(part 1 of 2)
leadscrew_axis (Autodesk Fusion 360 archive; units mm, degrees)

design "assy_leadscrew_axis" references "leadscrew_motor_mount", "HW_M5x30-FHCS", "HW_M5x40-FHCS", "HW_M3x16-SHCS", "HW_M3x8-SHCS", "HW_M5x10-FHCS", "HW_M3-Washer", "carriage_front_generic", "HW_M5 Nylock", "PP_TRNS_LeadNut-Block-8mm", "leadscrew_clip", "limit_mount", "lil_foot", "PP_ACTU_N17-Stepper-Leadscrew-300", "FRM-Extrusion-VSlot-2020-350", "circuit_mount_stepper_simple"
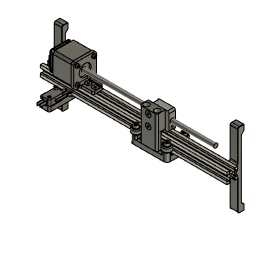
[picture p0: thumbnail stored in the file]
component_insert "Component Insert1"
joint "Assemble1" alignAngle -90 alignOffsetX 0 alignOffsetY 0 alignOffsetZ -6
component_insert "Component Insert2"
joint "Assemble2" alignAngle 0 alignOffsetX 0 alignOffsetY 80 alignOffsetZ 6
component_insert "Component Insert3"
joint "Assemble3" alignAngle -90 alignOffsetX 0 alignOffsetY 0 alignOffsetZ 0
component_insert "Component Insert4"
joint "Assemble4" alignAngle 180 alignOffsetX 0 alignOffsetY 0 alignOffsetZ 0
component_insert "Component Insert6"
joint "Assemble5" alignAngle 0 alignOffsetX 0 alignOffsetY 0 alignOffsetZ -10
component_insert "Component Insert7"
joint "Assemble6" alignAngle 270 alignOffsetX 0 alignOffsetY 53 alignOffsetZ 6
component_insert "Component Insert8"
joint "Assemble7" alignAngle 270 alignOffsetX 0 alignOffsetY 0 alignOffsetZ 0
joint "Assemble9" alignAngle 180 alignOffsetX 0 alignOffsetY 0 alignOffsetZ 0
component_insert "Component Insert9"
joint "Assemble10" alignAngle -90 alignOffsetX 0 alignOffsetY 0 alignOffsetZ 0
component_insert "Component Insert10"
component_insert "Component Insert11"
joint "Assemble11" alignAngle 0 alignOffsetX 0 alignOffsetY -10 alignOffsetZ 6
joint "Assemble12" alignAngle 0 alignOffsetX 0 alignOffsetY 10 alignOffsetZ 6
component_insert "Component Insert12"
joint "Assemble13" alignAngle 0 alignOffsetX 0 alignOffsetY 0 alignOffsetZ 0
component_insert "Component Insert13"
joint "Assemble14" alignAngle -90 alignOffsetX 0 alignOffsetY 0 alignOffsetZ 0
component_insert "Component Insert14"
component_insert "Component Insert15"
joint "Assemble15" alignAngle -90 alignOffsetX 0 alignOffsetY 0 alignOffsetZ 0
joint "Assemble16" alignAngle -90 alignOffsetX 0 alignOffsetY 0 alignOffsetZ 0
component_insert "Component Insert16"
component_insert "Component Insert17"
joint "Assemble17" alignAngle -90 alignOffsetX 0 alignOffsetY 0 alignOffsetZ 0
joint "Assemble18" alignAngle -90 alignOffsetX 0 alignOffsetY 0 alignOffsetZ 0
component_insert "Component Insert18"
component_insert "Component Insert19"
joint "Assemble19" alignAngle 90 alignOffsetX 0 alignOffsetY 0 alignOffsetZ 0
joint "Assemble20" alignAngle 90 alignOffsetX 0 alignOffsetY 0 alignOffsetZ 0
component_insert "Component Insert20"
component_insert "Component Insert21"
component_insert "Component Insert22"
joint "Assemble21" alignAngle 180 alignOffsetX 0 alignOffsetY 0 alignOffsetZ 0
joint "Assemble22" alignAngle -90 alignOffsetX 0 alignOffsetY 0 alignOffsetZ 0
joint "Assemble23" alignAngle -90 alignOffsetX 0 alignOffsetY 0 alignOffsetZ 0
component_insert "Component Insert23"
component_insert "Component Insert24"
joint "Assemble24" alignAngle 60 alignOffsetX 0 alignOffsetY 0 alignOffsetZ 0
joint "Assemble25" alignAngle 60 alignOffsetX 0 alignOffsetY 0 alignOffsetZ 0
component_insert "Component Insert25"
component_insert "Component Insert26"
component_insert "Component Insert27"
component_insert "Component Insert28"
joint "Assemble26" alignAngle 90 alignOffsetX 0 alignOffsetY 0 alignOffsetZ 0
joint "Assemble27" alignAngle -90 alignOffsetX 0 alignOffsetY 0 alignOffsetZ 0
joint "Assemble28" alignAngle -90 alignOffsetX 0 alignOffsetY 0 alignOffsetZ 0
joint "Assemble29" alignAngle -90 alignOffsetX 0 alignOffsetY 0 alignOffsetZ 0
component_insert "Component Insert29"
component_insert "Component Insert30"
component_insert "Component Insert31"
component_insert "Component Insert32"
joint "Assemble30" alignAngle 0 alignOffsetX 0 alignOffsetY 0 alignOffsetZ 0
joint "Assemble31" alignAngle 0 alignOffsetX 0 alignOffsetY 0 alignOffsetZ 0
joint "Assemble32" alignAngle 0 alignOffsetX 0 alignOffsetY 0 alignOffsetZ 0
joint "Assemble33" alignAngle 0 alignOffsetX 0 alignOffsetY 0 alignOffsetZ 0
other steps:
joint_origin "JointOrigin1"
joint_origin "JointOrigin2"

design "PP_TRNS_Mini-V-Wheel"
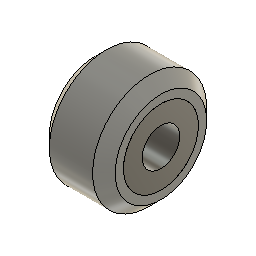
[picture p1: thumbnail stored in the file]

design "PP_TRNS_LeadNut-Block-8mm"
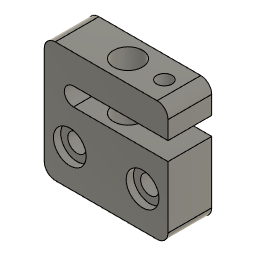
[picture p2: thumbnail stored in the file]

design "HW_M5x30-FHCS"
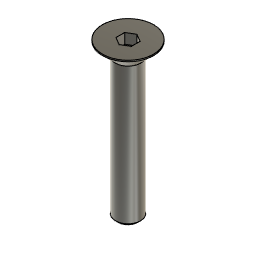
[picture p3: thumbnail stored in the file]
sketch "Sketch1" plane through (0, 0, 0) normal (0, 1, 0) x axis (1, 0, 0)
  line L1 (0, 30) -> (0, 0)
  line L2 (1.95, 30) -> (0, 30)
  line L3 (2.45, 29.5) -> (1.95, 30)
  line L4 (2.45, 2.8) -> (2.45, 29.5)
  line L5 (5, 0.25) -> (2.45, 2.8)
  line L6 (5, 0) -> (5, 0.25)
  line L7 (0, 0) -> (5, 0)
  point P1 (0, 0)
  point P2 (0, 0)
  point P9 (0, 0)
  point P3 (0, 30)
  point P4 (1.95, 30)
  point P8 (5, 0)
  point P7 (5, 0.25)
  coincident P1 P2
  vertical L1
  perpendicular L1 L2
  perpendicular L2 L4
  parallel L3 L5
  parallel L4 L6
  perpendicular L6 L7
  coincident P1 P9
  dimension "d1" distance P3 L4 = 2.45 (= "( 4.9 / 2 ) * 1 mm")
  dimension "d3" angle L2 L3 = 45
  dimension "d5" distance P4 L4 = 0.5
  dimension "d6" distance P2 P3 = 30
  dimension "d7" distance P8 P9 = 5 (= "( 10 / 2 ) * 1 mm")
  dimension "d9" distance P7 P8 = 0.25
revolve "Revolve1" sketch "Sketch1" AlongAngle 360
sketch "Sketch2" plane through (0, 0, 0) normal (0, 0, 1) x axis (-1, 0, 0)
  line L1 (0, -1.7321) -> (-1.5, -0.866)
  line L2 (1.5, -0.866) -> (0, -1.7321)
  line L3 (1.5, 0.866) -> (1.5, -0.866)
  line L4 (0, 1.7321) -> (1.5, 0.866)
  line L5 (-1.5, 0.866) -> (0, 1.7321)
  line L6 (-1.5, -0.866) -> (-1.5, 0.866)
  circle C1 centre (0, 0) radius 5
  point P1 (0, 0)
  point P9 (0, 0)
  coincident P1 P9
  vertical L6
  dimension "d12" distance L3 L6 = 3
extrude "Extrude1" cut sketch "Sketch2" profile of L1 L2 L3 L4 L5 L6 against normal blind 2

design "HW_M5x10-FHCS"
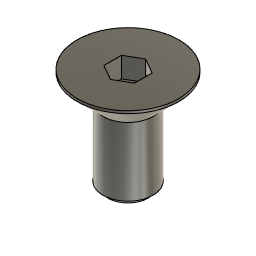
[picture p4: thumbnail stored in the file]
sketch "Sketch1" plane through (0, 0, 0) normal (0, 1, 0) x axis (1, 0, 0)
  line L1 (0, 10) -> (0, 0)
  line L2 (1.95, 10) -> (0, 10)
  line L3 (2.45, 9.5) -> (1.95, 10)
  line L4 (2.45, 2.8) -> (2.45, 9.5)
  line L5 (5, 0.25) -> (2.45, 2.8)
  line L6 (5, 0) -> (5, 0.25)
  line L7 (0, 0) -> (5, 0)
  point P1 (0, 0)
  point P2 (0, 0)
  point P9 (0, 0)
  point P3 (0, 10)
  point P4 (1.95, 10)
  point P8 (5, 0)
  point P7 (5, 0.25)
  coincident P1 P2
  vertical L1
  perpendicular L1 L2
  perpendicular L2 L4
  parallel L3 L5
  parallel L4 L6
  perpendicular L6 L7
  coincident P1 P9
  dimension "d1" distance P3 L4 = 2.45 (= "( 4.9 / 2 ) * 1 mm")
  dimension "d3" angle L2 L3 = 45
  dimension "d5" distance P4 L4 = 0.5
  dimension "d6" distance P2 P3 = 10
  dimension "d7" distance P8 P9 = 5 (= "( 10 / 2 ) * 1 mm")
  dimension "d9" distance P7 P8 = 0.25
revolve "Revolve1" sketch "Sketch1" AlongAngle 360
sketch "Sketch2" plane through (0, 0, 0) normal (0, 0, 1) x axis (-1, 0, 0)
  line L1 (0, -1.7321) -> (-1.5, -0.866)
  line L2 (1.5, -0.866) -> (0, -1.7321)
  line L3 (1.5, 0.866) -> (1.5, -0.866)
  line L4 (0, 1.7321) -> (1.5, 0.866)
  line L5 (-1.5, 0.866) -> (0, 1.7321)
  line L6 (-1.5, -0.866) -> (-1.5, 0.866)
  circle C1 centre (0, 0) radius 5
  point P1 (0, 0)
  point P9 (0, 0)
  coincident P1 P9
  vertical L6
  dimension "d12" distance L3 L6 = 3
extrude "Extrude1" cut sketch "Sketch2" profile of L1 L2 L3 L4 L5 L6 against normal blind 2

design "lil_foot"
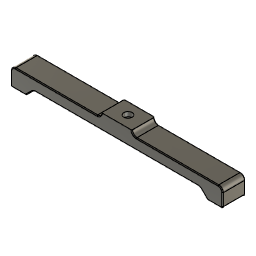
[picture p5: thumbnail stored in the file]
sketch "Sketch1" plane through (0, 0, 0) normal (0, 1, 0) x axis (1, 0, 0)
  line L1 (0, 0) -> (-10, 0)
  line L2 (-10, 3) -> (-10, 0)
  line L3 (-70, 3) -> (-10, 3)
  line L4 (-70, 15) -> (-70, 3)
  line L5 (-60, 15) -> (-70, 15)
  line L6 (-55, 10) -> (-60, 15)
  line L7 (0, 10) -> (-55, 10)
  line L8 (0, 0) -> (0, 10)
  line L9 (0, 0) -> (10, 0)
  line L10 (10, 3) -> (10, 0)
  line L11 (70, 3) -> (10, 3)
  line L12 (70, 15) -> (70, 3)
  line L13 (60, 15) -> (70, 15)
  line L14 (55, 10) -> (60, 15)
  line L15 (0, 10) -> (55, 10)
  point P1 (0, 0)
  point P9 (0, 0)
  point P10 (0, 0)
  point P2 (-10, 0)
  point P11 (10, 0)
  point P3 (-10, 3)
  point P13 (10, 3)
  point P4 (-70, 3)
  point P14 (70, 3)
  point P5 (-70, 15)
  point P15 (70, 15)
  point P6 (-60, 15)
  point P16 (60, 15)
  point P7 (-55, 10)
  point P17 (55, 10)
  point P8 (0, 10)
  point P18 (0, 10)
  point P12 (0, 0)
  horizontal L1
  perpendicular L1 L2
  perpendicular L2 L3
  perpendicular L3 L4
  perpendicular L4 L5
  perpendicular L4 L7
  perpendicular L7 L8
  coincident P1 P9
  coincident L8 P10
  coincident P1 P10
  symmetric P2 L8 P11
  symmetric P3 L8 P13
  symmetric P4 L8 P14
  symmetric P5 L8 P15
  symmetric P6 L8 P16
  symmetric P7 L8 P17
  symmetric P8 L8 P18
  symmetric L8 P10 P12
  dimension "d2" distance P2 P10 = 10
  dimension "d4" angle L6 L7 = 45
  dimension "d5" distance P5 P6 = 10
  dimension "d6" distance P6 P7 = 5
  dimension "d8" distance P5 P8 = 70 (= "( 140 / 2 ) * 1 mm")
  dimension "d9" distance P2 P3 = 3
  dimension "d11" distance P2 P5 = 15
  dimension "d12" distance P1 P8 = 10
extrude "Extrude1" new body sketch "Sketch1" profile of L1 L2 L3 L4 L5 L6 L7 L9 L10 L11 L12 L13 L14 L15 along normal blind 15
sketch "Sketch2" plane through (0, 0, 0) normal (0, 0, 1) x axis (-1, 0, 0)
  line L1 (-10, 0) -> (10, 0)
  line L2 (-10, -15) -> (-10, 0)
  line L3 (10, -15) -> (-10, -15)
  line L4 (10, 0) -> (10, -15)
  line L5 (0, -15) -> (0, 0)
  circle C1 centre (0, -7.5) radius 2.75
  circle C2 centre (0, -7.5) radius 5.25
  point P1 (0, 0)
  point P6 (0, 0)
  point P7 (0, -15)
  point P8 (0, -7.5)
  coincident P1 P6
  midpoint L3 P7
  midpoint L5 P8
  concentric C1 C2
  dimension "d15" diameter C2 = 10.5
  dimension "d16" diameter C1 = 5.5
extrude "Extrude2" cut sketch "Sketch2" profile of C1 to an object
extrude "Extrude3" cut sketch "Sketch2" profile of L2 L4 C1 C2 no distance stored from offset -5.5
chamfer "Chamfer1" distance 2.5
fillet "Fillet1" radius 3
fillet "Fillet2" radius 1
chamfer "Chamfer2" distance 0.5
named bodies: "lil_foot"

design "PP_ACTU_N17-Stepper-Leadscrew-300"
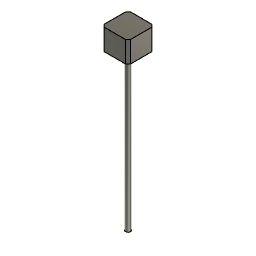
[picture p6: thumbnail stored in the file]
description: Nema 17 Stepper, 48mm Length Preferred, 5mm Shaft
sketch "Sketch1" plane through (0, 0, 0) normal (0, 0, 1) x axis (1, 0, 0)
  line L1 (-21.15, 21.15) -> (21.15, 21.15)
  line L2 (-21.15, -21.15) -> (-21.15, 21.15)
  line L3 (21.15, -21.15) -> (-21.15, -21.15)
  line L4 (21.15, 21.15) -> (21.15, -21.15)
  line L5 (-21.15, -21.15) -> (21.15, 21.15)
  line L6 (21.15, -21.15) -> (-21.15, 21.15)
  line L7 (15.5, 15.5) -> (-15.5, 15.5)
  line L8 (15.5, -15.5) -> (15.5, 15.5)
  line L9 (-15.5, -15.5) -> (15.5, -15.5)
  line L10 (-15.5, 15.5) -> (-15.5, -15.5)
  circle C1 centre (0, 0) radius 11
  circle C2 centre (-15.5, 15.5) radius 1.5
  circle C3 centre (-15.5, -15.5) radius 1.5
  circle C4 centre (15.5, -15.5) radius 1.5
  circle C5 centre (15.5, 15.5) radius 1.5
  circle C6 centre (0, 0) radius 4
  point P6 (0, 0)
  point P1 (0, 0)
  point P7 (0, 0)
  point P10 (15.5, -15.5)
  point P8 (-15.5, 15.5)
  point P9 (15.5, 15.5)
  point P12 (-15.5, 15.5)
  point P11 (-15.5, -15.5)
  point P13 (-15.5, -15.5)
  point P14 (15.5, -15.5)
  point P15 (15.5, 15.5)
  point P2 (21.15, 21.15)
  point P3 (-21.15, 21.15)
  perpendicular L1 L2
  parallel L1 L3
  parallel L2 L4
  horizontal L1
  coincident L5 P6
  coincident L6 P6
  coincident P1 P6
  equal L1 L2
  coincident P6 P7
  horizontal L7
  vertical L8
  horizontal L9
  vertical L10
  coincident L6 P10
  coincident L6 P8
  coincident L5 P9
  coincident P8 P12
  coincident P11 P13
  coincident P10 P14
  coincident P9 P15
  equal C2 C5
  equal C2 C3
  equal C2 C4
  concentric C1 C6
  dimension "d1" distance P2 P3 = 42.3
  dimension "d2" diameter C1 = 22
  dimension "d3" distance P8 P9 = 31
  dimension "d4" diameter C2 = 3
  dimension "d5" diameter C6 = 8
  dimension "d15" alignAngle = 0
  dimension "d16" alignOffsetX = 0
  dimension "d17" alignOffsetY = 0
  dimension "d18" alignOffsetZ = 8
  dimension "d19" alignAngle = 0
  dimension "d20" alignOffsetX = 0
  dimension "d21" alignOffsetY = 0
  dimension "d22" alignOffsetZ = 0
extrude "Extrude1" new body sketch "Sketch1" profile of L1 L2 L3 L4 C1 C2 C3 C4 C5 C6 along normal blind 34
extrude "Extrude2" cut sketch "Sketch1" profile of C2 C3 C4 C5 along normal blind 5
extrude "Extrude3" add sketch "Sketch1" profile of C1 C6 against normal blind 2
extrude "Extrude4" add sketch "Sketch1" profile of C6 against normal blind 250
chamfer "Chamfer1" distance 4

design "FRM-Extrusion-VSlot-2020-350"
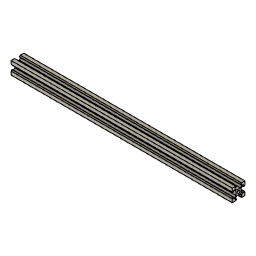
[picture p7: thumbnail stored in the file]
parameter "d90" = 4
parameter "d92" = 0.75 (= "( 1.5 / 2 ) * 1 mm")
sketch "Sketch4" plane through (0, 0, 0) normal (1, 0, 0) x axis (0, 1, 0)
  line L1 (20, 0) -> (0, 0)
  line L2 (20, 20) -> (20, 0)
  line L3 (0, 20) -> (20, 20)
  line L4 (0, 0) -> (0, 20)
  line L5 (10, 0) -> (10, 20)
  line L6 (0, 10) -> (20, 10)
  line L7 (15.5, 18.2) -> (13.125, 18.2)
  line L8 (12.9393, 14) -> (15.5, 16.5607)
  line L9 (10, 14) -> (12.9393, 14)
  line L10 (20, 20) -> (10, 10)
  line L11 (13.125, 18.545) -> (13.125, 18.2)
  line L12 (14.58, 20) -> (13.125, 18.545)
  line L13 (15.5, 16.5607) -> (15.5, 18.2)
  line L14 (20, 14.58) -> (18.545, 13.125)
  line L15 (18.545, 13.125) -> (18.2, 13.125)
  line L16 (16.5607, 15.5) -> (18.2, 15.5)
  line L17 (14, 12.9393) -> (16.5607, 15.5)
  line L18 (14, 10) -> (14, 12.9393)
  line L19 (18.2, 15.5) -> (18.2, 13.125)
  line L20 (5.42, 20) -> (6.875, 18.545)
  line L21 (6.875, 18.545) -> (6.875, 18.2)
  line L22 (4.5, 18.2) -> (6.875, 18.2)
  line L23 (4.5, 16.5607) -> (4.5, 18.2)
  line L24 (10, 14) -> (7.0607, 14)
  line L25 (7.0607, 14) -> (4.5, 16.5607)
  line L26 (0, 14.58) -> (1.455, 13.125)
  line L27 (1.455, 13.125) -> (1.8, 13.125)
  line L28 (1.8, 15.5) -> (1.8, 13.125)
  line L29 (3.4393, 15.5) -> (1.8, 15.5)
  line L30 (6, 10) -> (6, 12.9393)
  line L31 (6, 12.9393) -> (3.4393, 15.5)
  line L32 (5.42, 0) -> (6.875, 1.455)
  line L33 (6.875, 1.455) -> (6.875, 1.8)
  line L34 (4.5, 1.8) -> (6.875, 1.8)
  line L35 (4.5, 3.4393) -> (4.5, 1.8)
  line L36 (7.0607, 6) -> (4.5, 3.4393)
  line L37 (10, 6) -> (7.0607, 6)
  line L38 (14.58, 0) -> (13.125, 1.455)
  line L39 (13.125, 1.455) -> (13.125, 1.8)
  line L40 (15.5, 1.8) -> (13.125, 1.8)
  line L41 (15.5, 3.4393) -> (15.5, 1.8)
  line L42 (12.9393, 6) -> (15.5, 3.4393)
  line L43 (10, 6) -> (12.9393, 6)
  line L44 (0, 5.42) -> (1.455, 6.875)
  line L45 (1.455, 6.875) -> (1.8, 6.875)
  line L46 (1.8, 4.5) -> (1.8, 6.875)
  line L47 (3.4393, 4.5) -> (1.8, 4.5)
  line L48 (6, 10) -> (6, 7.0607)
  line L49 (6, 7.0607) -> (3.4393, 4.5)
  line L50 (20, 5.42) -> (18.545, 6.875)
  line L51 (18.545, 6.875) -> (18.2, 6.875)
  line L52 (18.2, 4.5) -> (18.2, 6.875)
  line L53 (16.5607, 4.5) -> (18.2, 4.5)
  line L54 (14, 10) -> (14, 7.0607)
  line L55 (14, 7.0607) -> (16.5607, 4.5)
  circle C1 centre (10, 10) radius 2.2
  point P1 (0, 0)
  point P2 (0, 0)
  point P6 (10, 20)
  point P7 (10, 0)
  point P8 (20, 10)
  point P9 (0, 10)
  point P12 (10, 14)
  point P13 (10, 10)
  point P14 (10, 10)
  point P16 (14.58, 20)
  point P10 (13.125, 18.2)
  point P21 (18.2, 13.125)
  point P11 (12.9393, 14)
  point P24 (14, 12.9393)
  point P25 (14, 10)
  point P15 (13.125, 18.545)
  point P19 (18.545, 13.125)
  point P20 (20, 14.58)
  point P17 (15.5, 18.2)
  point P22 (18.2, 15.5)
  point P18 (15.5, 16.5607)
  point P23 (16.5607, 15.5)
  point P28 (6.875, 18.2)
  point P31 (7.0607, 14)
  point P32 (10, 14)
  point P26 (6.875, 18.545)
  point P27 (5.42, 20)
  point P29 (4.5, 18.2)
  point P30 (4.5, 16.5607)
  point P33 (1.455, 13.125)
  point P34 (0, 14.58)
  point P35 (1.8, 13.125)
  point P36 (1.8, 15.5)
  point P37 (3.4393, 15.5)
  point P38 (6, 12.9393)
  point P39 (6, 10)
  point P49 (13.125, 1.8)
  point P52 (12.9393, 6)
  point P53 (10, 6)
  point P47 (13.125, 1.455)
  point P48 (14.58, 0)
  point P50 (15.5, 1.8)
  point P51 (15.5, 3.4393)
  point P61 (18.545, 6.875)
  point P62 (20, 5.42)
  point P63 (18.2, 6.875)
  point P64 (18.2, 4.5)
  point P65 (16.5607, 4.5)
  point P66 (14, 7.0607)
  point P67 (14, 10)
  point P40 (6.875, 1.455)
  point P41 (5.42, 0)
  point P42 (6.875, 1.8)
  point P43 (4.5, 1.8)
  point P44 (4.5, 3.4393)
  point P45 (7.0607, 6)
  point P46 (10, 6)
  point P54 (1.455, 6.875)
  point P55 (0, 5.42)
  point P56 (1.8, 6.875)
  point P57 (1.8, 4.5)
  point P58 (3.4393, 4.5)
  point P59 (6, 7.0607)
  point P60 (6, 10)
  point P3 (20, 0)
  point P4 (20, 20)
  horizontal L1
  vertical L2
  horizontal L3
  vertical L4
  coincident P1 P2
  equal L1 L4
  midpoint L3 P6
  midpoint L1 P7
  midpoint L2 P8
  midpoint L4 P9
  coincident L5 P12
  perpendicular L5 L9
  midpoint L5 P13
  coincident P13 P14
  parallel L8 L10
  perpendicular L7 L11
  coincident L3 P16
  parallel L10 L12
  perpendicular L7 L13
  horizontal L7
  symmetric P10 L10 P21
  symmetric P11 L10 P24
  symmetric P12 L10 P25
  symmetric L10 P15 P19
  symmetric L10 P16 P20
  symmetric L10 P17 P22
  symmetric L10 P18 P23
  symmetric L5 P10 P28
  symmetric L5 P11 P31
  symmetric L5 P12 P32
  symmetric L5 P15 P26
  symmetric L5 P16 P27
  symmetric L5 P17 P29
  symmetric L5 P18 P30
  symmetric L5 P19 P33
  symmetric L5 P20 P34
  symmetric L5 P21 P35
  symmetric L5 P22 P36
  symmetric L5 P23 P37
  symmetric L5 P24 P38
  symmetric L5 P25 P39
  symmetric L6 P10 P49
  symmetric L6 P11 P52
  symmetric L6 P12 P53
  symmetric L6 P15 P47
  symmetric L6 P16 P48
  symmetric L6 P17 P50
  symmetric L6 P18 P51
  symmetric L6 P19 P61
  symmetric L6 P20 P62
  symmetric L6 P21 P63
  symmetric L6 P22 P64
  symmetric L6 P23 P65
  symmetric L6 P24 P66
  symmetric L6 P25 P67
  symmetric L6 P26 P40
  symmetric L6 P27 P41
  symmetric L6 P28 P42
  symmetric L6 P29 P43
  symmetric L6 P30 P44
  symmetric L6 P31 P45
  symmetric L6 P32 P46
  symmetric L6 P33 P54
  symmetric L6 P34 P55
  symmetric L6 P35 P56
  symmetric L6 P36 P57
  symmetric L6 P37 P58
  symmetric L6 P38 P59
  symmetric L6 P39 P60
  dimension "d177" distance P2 P3 = 20
  dimension "d178" diameter C1 = 4.4
  dimension "d181" distance P4 L8 = 0.75 (= "( 1.5 / 2 ) * 1 mm")
  dimension "d182" distance L9 P13 = 4
  dimension "d215" distance P6 L13 = 5.5 (= "( 11 / 2 ) * 1 mm")
  dimension "d216" distance P6 P10 = 3.125 (= "( 6.25 / 2 ) * 1 mm")
  dimension "d217" distance P6 P16 = 4.58 (= "( 9.16 / 2 ) * 1 mm")
  dimension "d219" distance P4 P17 = 1.8
  dimension "d220" distance P10 L9 = 4.2
  dimension "d32" distance = 3 (= "( 6 / 2 ) * 1 mm")
  dimension "d33" distance = 3 (= "d32")
  dimension "d34" distance = 3 (= "d33")
  dimension "d35" distance = 3 (= "d32")
  dimension "d43" distance = 2
  dimension "d44" distance = 2 (= "d43")
extrude "Extrude3" new body sketch "Sketch4" profile of L1 L2 L3 L4 L7 L8 L9 C1 L11 L12 L13 L14 L15 L16 L17 L18 L19 L20 L21 L22 L23 L24 L25 L26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 along normal blind 350
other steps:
step "Extrude" AlongDistance -1.5 TaperAngle 0
step "Fillet" ChordLen 3
step "Chamfer5" Distance 0.5
step "Chamfer6" Distance 1

design "HW_M3x8-SHCS"
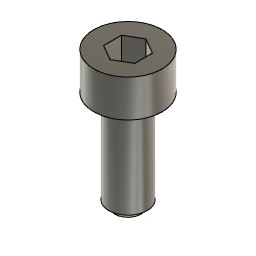
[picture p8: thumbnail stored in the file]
sketch "Sketch1" plane through (0, 0, 0) normal (0, 1, 0) x axis (1, 0, 0)
  line L1 (0, 8) -> (0, -3)
  line L2 (1.05, 8) -> (0, 8)
  line L3 (1.55, 7.5) -> (1.05, 8)
  line L4 (1.55, 0) -> (1.55, 7.5)
  line L5 (2.75, 0) -> (1.55, 0)
  line L6 (2.75, -3) -> (2.75, 0)
  line L7 (0, -3) -> (2.75, -3)
  point P1 (0, 0)
  point P4 (1.05, 8)
  point P5 (1.55, 7.5)
  point P3 (0, 8)
  point P7 (2.75, 0)
  point P8 (2.75, -3)
  point P2 (0, -3)
  vertical L1
  perpendicular L1 L2
  perpendicular L2 L4
  perpendicular L4 L5
  perpendicular L5 L6
  horizontal L7
  coincident P1 L1
  coincident P1 L5
  dimension "d1" distance P1 L2 = 8
  dimension "d2" angle L2 L3 = 45
  dimension "d3" distance P4 P5 = 0.5
  dimension "d4" distance P3 L4 = 1.55 (= "( 3.1 / 2 ) * 1 mm")
  dimension "d5" distance P7 P8 = 3
  dimension "d6" distance P2 P8 = 2.75 (= "( 5.5 / 2 ) * 1 mm")
revolve "Revolve1" sketch "Sketch1" AlongAngle 360
sketch "Sketch2" plane through (0, 0, 3) normal (0, 0, 1) x axis (-1, 0, 0)
  line L1 (0, -1.4434) -> (-1.25, -0.7217)
  line L2 (1.25, -0.7217) -> (0, -1.4434)
  line L3 (1.25, 0.7217) -> (1.25, -0.7217)
  line L4 (0, 1.4434) -> (1.25, 0.7217)
  line L5 (-1.25, 0.7217) -> (0, 1.4434)
  line L6 (-1.25, -0.7217) -> (-1.25, 0.7217)
  circle C1 centre (0, 0) radius 2.75
  point P1 (0, 0)
  point P9 (0, 0)
  point P5 (1.25, -0.7217)
  coincident P1 P9
  vertical L6
  dimension "d8" distance P5 L6 = 2.5
extrude "Extrude1" cut sketch "Sketch2" profile of L1 L2 L3 L4 L5 L6 against normal blind 2

design "carriage_front_generic" references "HW_M5x20-SHCS", "PP_TRNS_Mini-V-Wheel"
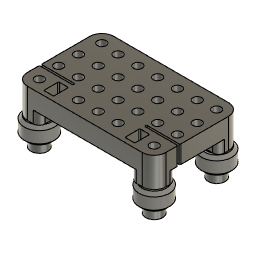
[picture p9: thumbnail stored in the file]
sketch "Sketch1" plane through (0, 0, 0) normal (0, 0, 1) x axis (1, 0, 0)
  line L1 (0, -21.8) -> (0, 21.8)
  line L2 (-18, -12.01) -> (-23, -12.01)
  line L3 (-18, -19.54) -> (-18, -12.01)
  line L4 (-23, -19.54) -> (-18, -19.54)
  line L5 (-23, -12.01) -> (-23, -19.54)
  line L6 (-1.8225, 21.8) -> (0, 21.8)
  line L7 (-35, 21.8) -> (-1.8225, 21.8)
  line L8 (-35, -8.75) -> (-35, 21.8)
  line L9 (-18, -8.75) -> (-35, -8.75)
  line L10 (-18, -9.75) -> (-18, -8.75)
  line L11 (-35, -9.75) -> (-18, -9.75)
  line L12 (-35, -21.8) -> (-35, -9.75)
  line L13 (0, -21.8) -> (-35, -21.8)
  line L14 (-29, 15.8) -> (-29, -15.75)
  line L15 (0, 10) -> (-35, 10)
  line L16 (0, -10) -> (-35, -10)
  line L17 (-23, -10.75) -> (-35, -10.75)
  line L18 (-23, -12.01) -> (-23, -10.75)
  line L19 (-23, -21.8) -> (-23, -19.54)
  line L20 (-23, 10.75) -> (-35, 10.75)
  line L21 (-23, 21.8) -> (-23, 10.75)
  circle C1 centre (-29, 15.8) radius 2.2
  circle C2 centre (-29, -15.75) radius 2.2
  circle C3 centre (-29, -15.75) radius 5
  circle C4 centre (-29, 15.8) radius 5
  circle C5 centre (-29, 15.8) radius 3.7
  circle C6 centre (-29, -15.75) radius 3.7
  circle C7 centre (0, 15) radius 2.2
  point P1 (0, 0)
  point P3 (0, -21.8)
  point P19 (0, -21.8)
  point P5 (-29, -15.75)
  point P20 (-29, -15.75)
  point P11 (-29, 15.8)
  point P21 (-29, 15.8)
  point P7 (-18, -12.01)
  point P22 (-35, 10)
  point P23 (0, 10)
  point P24 (-35, -10)
  point P25 (0, -10)
  point P26 (-35, -10.75)
  point P6 (-23, -12.01)
  point P28 (-23, -12.01)
  point P29 (-23, -21.8)
  point P30 (-35, 10.75)
  point P32 (-23, 21.8)
  point P35 (0, 15)
  point P4 (-29, 15.8)
  point P13 (-35, 21.8)
  point P10 (-29, -15.75)
  point P2 (0, 21.8)
  point P15 (-18, -8.75)
  point P16 (-18, -9.75)
  vertical L1
  coincident P1 L1
  equal C1 C2
  horizontal L2
  vertical L3
  horizontal L4
  vertical L5
  concentric C2 C3
  concentric C1 C4
  equal C3 C4
  perpendicular L1 L6
  perpendicular L1 L7
  perpendicular L7 L8
  perpendicular L1 L9
  perpendicular L9 L10
  perpendicular L10 L11
  perpendicular L9 L12
  perpendicular L12 L13
  coincident P3 P19
  midpoint P1 L1
  coincident P5 P20
  coincident P11 P21
  vertical L14
  coincident P7 L10
  coincident L8 P22
  coincident L1 P23
  perpendicular L1 L15
  coincident L12 P24
  coincident L1 P25
  perpendicular L1 L16
  coincident L12 P26
  perpendicular L14 L17
  perpendicular L17 L18
  coincident P6 P28
  coincident L13 P29
  perpendicular L13 L19
  coincident L8 P30
  perpendicular L14 L20
  coincident L7 P32
  perpendicular L7 L21
  coincident P28 L21
  concentric C1 C5
  concentric C3 C6
  equal C5 C6
  coincident L1 P35
  dimension "d1" distance P1 P4 = 15.8
  dimension "d2" distance P1 P5 = 15.75 (= "d1 - 0.05 mm")
  dimension "d3" diameter C1 = 4.4
  dimension "d4" diameter C4 = 10
  dimension "d7" distance P4 P13 = 6
  dimension "d8" distance P4 P13 = 6
  dimension "d9" distance P10 L11 = 6
  dimension "d10" distance P10 L12 = 6
  dimension "d11" distance P2 P13 = 35
  dimension "d12" distance P15 P16 = 1
  dimension "d13" distance L5 P10 = 6
  dimension "d14" distance L2 L11 = 2.26
  dimension "d15" distance L4 L13 = 2.26 (= "d14")
  dimension "d16" distance P6 P7 = 5
  dimension "d17" distance P1 L15 = 10
  dimension "d18" distance P1 P25 = 10
  dimension "d19" distance P1 L17 = 10.75
  dimension "d20" distance P1 P30 = 10.75 (= "d19")
  dimension "d28" distance C1 C5 = 1.5
  dimension "d73" diameter C7 = 4.4
  dimension "d76" distance P1 P35 = 15
extrude "Extrude1" new body sketch "Sketch1" profile of L1 C1 C2 L2 L3 L4 L5 L6 L7 L8 L9 L10 L11 L12 L13 L17 L18 L19 L20 L21 blind 9 from offset 11 bodies "carriage_front_generic"
extrude "Extrude2" add sketch "Sketch1" profile of C1 C2 L5 L7 L8 L12 L13 L17 L18 L19 L20 L21 to an object from offset 4.4 (= "( 8.8 / 2 ) * 1 mm")
extrude "Extrude3" sketch "Sketch1" profile of L5 L7 L8 L12 L13 L17 L18 L19 L20 L21 C5 C6 blind 0.6
fillet "Fillet1" radius 0.5
fillet "Fillet2" radius 6
fillet "Fillet3" radius 3
extrude "Extrude4" cut sketch "Sketch1" profile of L1 C7 no distance stored
chamfer "Chamfer3" distance 1.5 distance 0.5
rectangular_pattern "R-Pattern1" uSpaceDistance 10 vSpaceDistance 10
mirror "Mirror1" mirrorStitchTolerance 0.1
component_insert "Component Insert2"
component_insert "Component Insert3"
component_insert "Component Insert4"
component_insert "Component Insert5"
joint "Assemble1" alignAngle 0 alignOffsetX 0 alignOffsetY 0 alignOffsetZ 0
joint "Assemble2" alignAngle 0 alignOffsetX 0 alignOffsetY 0 alignOffsetZ 0
joint "Assemble3" alignAngle 180 alignOffsetX 0 alignOffsetY 0 alignOffsetZ 0
joint "Assemble4" alignAngle 180 alignOffsetX 0 alignOffsetY 0 alignOffsetZ 0
component_insert "Component Insert11"
component_insert "Component Insert12"
component_insert "Component Insert13"
component_insert "Component Insert14"
joint "Assemble9" alignAngle 180 alignOffsetX 0 alignOffsetY 0 alignOffsetZ 0
joint "Assemble10" alignAngle 0 alignOffsetX 0 alignOffsetY 0 alignOffsetZ 0
joint "Assemble11" alignAngle 180 alignOffsetX 0 alignOffsetY 0 alignOffsetZ 0
joint "Assemble12" alignAngle 0 alignOffsetX 0 alignOffsetY 0 alignOffsetZ 0
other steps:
joint_origin "JointOrigin1"
joint_origin "JointOrigin2"
joint_origin "JointOrigin4"
joint_origin "JointOrigin5"
named bodies: "carriage_front_generic"

design "HW_M5x40-FHCS"
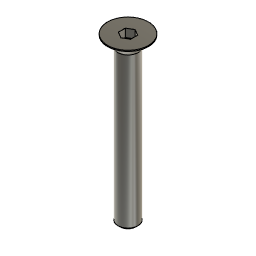
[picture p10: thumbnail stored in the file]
sketch "Sketch1" plane through (0, 0, 0) normal (0, 1, 0) x axis (1, 0, 0)
  line L1 (0, 40) -> (0, 0)
  line L2 (1.95, 40) -> (0, 40)
  line L3 (2.45, 39.5) -> (1.95, 40)
  line L4 (2.45, 2.8) -> (2.45, 39.5)
  line L5 (5, 0.25) -> (2.45, 2.8)
  line L6 (5, 0) -> (5, 0.25)
  line L7 (0, 0) -> (5, 0)
  point P1 (0, 0)
  point P2 (0, 0)
  point P9 (0, 0)
  point P3 (0, 40)
  point P4 (1.95, 40)
  point P8 (5, 0)
  point P7 (5, 0.25)
  coincident P1 P2
  vertical L1
  perpendicular L1 L2
  perpendicular L2 L4
  parallel L3 L5
  parallel L4 L6
  perpendicular L6 L7
  coincident P1 P9
  dimension "d1" distance P3 L4 = 2.45 (= "( 4.9 / 2 ) * 1 mm")
  dimension "d3" angle L2 L3 = 45
  dimension "d5" distance P4 L4 = 0.5
  dimension "d6" distance P2 P3 = 40
  dimension "d7" distance P8 P9 = 5 (= "( 10 / 2 ) * 1 mm")
  dimension "d9" distance P7 P8 = 0.25
revolve "Revolve1" sketch "Sketch1" AlongAngle 360
sketch "Sketch2" plane through (0, 0, 0) normal (0, 0, 1) x axis (-1, 0, 0)
  line L1 (0, -1.7321) -> (-1.5, -0.866)
  line L2 (1.5, -0.866) -> (0, -1.7321)
  line L3 (1.5, 0.866) -> (1.5, -0.866)
  line L4 (0, 1.7321) -> (1.5, 0.866)
  line L5 (-1.5, 0.866) -> (0, 1.7321)
  line L6 (-1.5, -0.866) -> (-1.5, 0.866)
  circle C1 centre (0, 0) radius 5
  point P1 (0, 0)
  point P9 (0, 0)
  coincident P1 P9
  vertical L6
  dimension "d12" distance L3 L6 = 3
extrude "Extrude1" cut sketch "Sketch2" profile of L1 L2 L3 L4 L5 L6 against normal blind 2

design "circuit_modular_stepper"
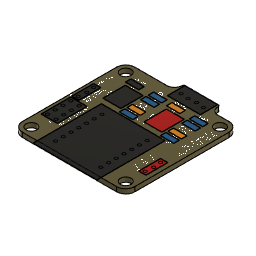
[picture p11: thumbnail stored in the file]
sketch "Outline" plane through (0, 0, 0) normal (0, 0, 1) x axis (1, 0, 0)
  line L1 (35, 1) -> (4, 1)
  line L2 (38, 35) -> (38, 4)
  line L3 (31, 38) -> (35, 38)
  line L4 (17.5, 41) -> (28.5, 41)
  line L5 (4, 38) -> (14.5, 38)
  line L6 (1, 4) -> (1, 35)
  arc A1 centre (4, 4) radius 3 clockwise from (4, 1) to (1, 4)
  arc A2 centre (35, 4) radius 3 clockwise from (38, 4) to (35, 1)
  arc A3 centre (35, 35) radius 3 clockwise from (35, 38) to (38, 35)
  arc A4 centre (31.25, 40.25) radius 2.2638 clockwise from (31, 38) to (29, 40.5)
  arc A5 centre (28.5, 40.5) radius 0.5 clockwise from (28.5, 41) to (29, 40.5)
  arc A6 centre (17.5, 40.5) radius 0.5 clockwise from (17, 40.5) to (17.5, 41)
  arc A7 centre (14.5, 40.5) radius 2.5 clockwise from (17, 40.5) to (14.5, 38)
  arc A8 centre (4, 35) radius 3 clockwise from (1, 35) to (4, 38)
canvas "Canvas1"
canvas "Canvas2"
pcbhole "PCBHole1" HoleDepth 1.606 HoleDiameter 3.5 TipAngle 10313.2
pcbhole "PCBHole2" HoleDepth 1.606 HoleDiameter 3.5 TipAngle 10313.2
pcbhole "PCBHole3" HoleDepth 1.606 HoleDiameter 3.5 TipAngle 10313.2
pcbhole "PCBHole4" HoleDepth 1.606 HoleDiameter 3.5 TipAngle 10313.2
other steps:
pcbextrude "PCBExtrude1"
pcbextrude "PCBExtrude1"
extrude "Extrude1" sketch "Outline" blind 1.5 bodies "Board"
box_primitive "BoxPrimitive1" DistanceX 7.1628 DistanceY 2.3368 DistanceZ 0.1 OffsetDistanceX 0 OffsetDistanceY 0
box_primitive "BoxPrimitive1" DistanceX 10.827 DistanceY 5.727 DistanceZ 0.1 OffsetDistanceX 0 OffsetDistanceY 0
box_primitive "BoxPrimitive1" DistanceX 5.353 DistanceY 9.7028 DistanceZ 0.1 OffsetDistanceX 0 OffsetDistanceY 0
box_primitive "BoxPrimitive1" DistanceX 4.4 DistanceY 1.8 DistanceZ 0.1 OffsetDistanceX 0 OffsetDistanceY 0
box_primitive "BoxPrimitive1" DistanceX 7.35 DistanceY 5.8597 DistanceZ 0.1 OffsetDistanceX 0 OffsetDistanceY 0
box_primitive "BoxPrimitive1" DistanceX 22.4638 DistanceY 20.955 DistanceZ 0.1 OffsetDistanceX 0 OffsetDistanceY 0
pcbextrude "PCBExtrude1"
pcbextrude "PCBExtrude2" bodies "CopperHoles"
create_component "CreateComponent1"
create_component "CreateComponent2"
create_component "CreateComponent3"
create_component "CreateComponent4"
create_component "CreateComponent1"
create_component "CreateComponent2"
create_component "CreateComponent3"
create_component "CreateComponent4"
create_component "CreateComponent5"
create_component "CreateComponent6"
as_built_joint "As-built1"
named bodies: "Board", "CopperHoles"

design "HW_M5x20-SHCS"
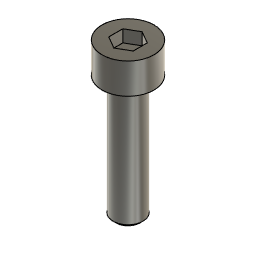
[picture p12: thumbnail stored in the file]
sketch "Sketch1" plane through (0, 0, 0) normal (0, 1, 0) x axis (1, 0, 0)
  line L1 (0, 20) -> (0, -5)
  line L2 (1.95, 20) -> (0, 20)
  line L3 (2.45, 19.5) -> (1.95, 20)
  line L4 (2.45, 0) -> (2.45, 19.5)
  line L5 (4.25, 0) -> (2.45, 0)
  line L6 (4.25, -5) -> (4.25, 0)
  line L7 (0, -5) -> (4.25, -5)
  point P1 (0, 0)
  point P4 (1.95, 20)
  point P5 (2.45, 19.5)
  point P3 (0, 20)
  point P7 (4.25, 0)
  point P8 (4.25, -5)
  point P2 (0, -5)
  vertical L1
  perpendicular L1 L2
  perpendicular L2 L4
  perpendicular L4 L5
  perpendicular L5 L6
  horizontal L7
  coincident P1 L1
  coincident P1 L5
  dimension "d1" distance P1 L2 = 20
  dimension "d2" angle L2 L3 = 45
  dimension "d3" distance P4 P5 = 0.5
  dimension "d4" distance P3 L4 = 2.45 (= "( 4.9 / 2 ) * 1 mm")
  dimension "d5" distance P7 P8 = 5
  dimension "d6" distance P2 P8 = 4.25 (= "( 8.5 / 2 ) * 1 mm")
revolve "Revolve1" sketch "Sketch1" AlongAngle 360
sketch "Sketch2" plane through (0, 0, 5) normal (0, 0, 1) x axis (-1, 0, 0)
  line L1 (0, -2.3094) -> (-2, -1.1547)
  line L2 (2, -1.1547) -> (0, -2.3094)
  line L3 (2, 1.1547) -> (2, -1.1547)
  line L4 (0, 2.3094) -> (2, 1.1547)
  line L5 (-2, 1.1547) -> (0, 2.3094)
  line L6 (-2, -1.1547) -> (-2, 1.1547)
  circle C1 centre (0, 0) radius 4.25
  point P1 (0, 0)
  point P9 (0, 0)
  point P5 (2, -1.1547)
  coincident P1 P9
  vertical L6
  dimension "d8" distance P5 L6 = 4
extrude "Extrude1" cut sketch "Sketch2" profile of L1 L2 L3 L4 L5 L6 against normal blind 2

design "HW_M5 Nylock"
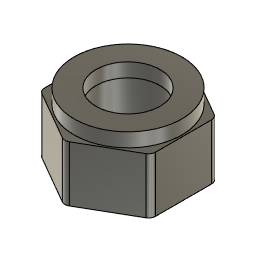
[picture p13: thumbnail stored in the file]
sketch "Sketch1" plane through (0, 0, 0) normal (0, 0, 1) x axis (1, 0, 0)
  line L1 (0, 4.6188) -> (4, 2.3094)
  line L2 (-4, 2.3094) -> (0, 4.6188)
  line L3 (-4, -2.3094) -> (-4, 2.3094)
  line L4 (0, -4.6188) -> (-4, -2.3094)
  line L5 (4, -2.3094) -> (0, -4.6188)
  line L6 (4, 2.3094) -> (4, -2.3094)
  circle C1 centre (0, 0) radius 2.55
  circle C2 centre (0, 0) radius 3.875
  circle C3 centre (0, 0) radius 2.3
  point P1 (0, 0)
  point P8 (0, 0)
  point P9 (0, 0)
  point P4 (-4, 2.3094)
  coincident P1 P8
  vertical L6
  coincident P8 P9
  concentric C1 C2
  concentric C1 C3
  dimension "d1" distance P4 L6 = 8
  dimension "d2" diameter C1 = 5.1
  dimension "d5" diameter C2 = 7.75
  dimension "d9" distance C1 C3 = 0.25
extrude "Extrude1" new body sketch "Sketch1" profile of L1 L2 L3 L4 L5 L6 C1 along normal blind 4
extrude "Extrude2" sketch "Sketch1" profile of C1 C2 C3 blind 1
fillet "Fillet1" radius 0.5

design "circuit_mount_stepper_simple" references "circuit_modular_stepper"
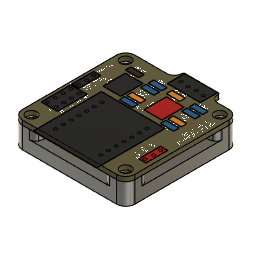
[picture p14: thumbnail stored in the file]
sketch "Sketch1" plane through (0, 0, 0) normal (0, 0, 1) x axis (1, 0, 0)
  line L1 (-18.5, 18.5) -> (18.5, 18.5)
  line L2 (-18.5, -18.5) -> (-18.5, 18.5)
  line L3 (18.5, -18.5) -> (-18.5, -18.5)
  line L4 (18.5, 18.5) -> (18.5, -18.5)
  line L5 (-18.5, -18.5) -> (18.5, 18.5)
  line L6 (18.5, -18.5) -> (-18.5, 18.5)
  line L7 (15.5, 15.5) -> (-15.5, 15.5)
  line L8 (15.5, -15.5) -> (15.5, 15.5)
  line L9 (-15.5, -15.5) -> (15.5, -15.5)
  line L10 (-15.5, 15.5) -> (-15.5, -15.5)
  circle C1 centre (15.5, 15.5) radius 1.7
  circle C2 centre (-15.5, 15.5) radius 1.7
  circle C3 centre (-15.5, -15.5) radius 1.7
  circle C4 centre (15.5, -15.5) radius 1.7
  circle C5 centre (-15.5, 15.5) radius 4.5
  circle C6 centre (15.5, 15.5) radius 4.5
  circle C7 centre (15.5, -15.5) radius 4.5
  circle C8 centre (-15.5, -15.5) radius 4.5
  circle C9 centre (0, 0) radius 15
  circle C10 centre (0, 0) radius 2.5
  circle C11 centre (0, 0) radius 4
  circle C12 centre (0, 0) radius 6.5
  point P6 (0, 0)
  point P1 (0, 0)
  point P9 (15.5, -15.5)
  point P7 (-15.5, 15.5)
  point P8 (15.5, 15.5)
  point P11 (15.5, 15.5)
  point P12 (-15.5, 15.5)
  point P10 (-15.5, -15.5)
  point P13 (-15.5, -15.5)
  point P14 (15.5, -15.5)
  point P19 (0, 0)
  point P21 (0, 0)
  point P2 (18.5, 18.5)
  point P3 (-18.5, 18.5)
  horizontal L1
  perpendicular L1 L2
  parallel L1 L3
  parallel L2 L4
  coincident L5 P6
  coincident L6 P6
  coincident P1 P6
  equal L1 L4
  horizontal L7
  vertical L8
  horizontal L9
  vertical L10
  coincident L6 P9
  coincident L6 P7
  coincident L5 P8
  equal C3 C4
  equal C1 C4
  equal C1 C2
  coincident P8 P11
  coincident P7 P12
  coincident P10 P13
  coincident P9 P14
  concentric C2 C5
  concentric C1 C6
  concentric C4 C7
  concentric C3 C8
  equal C5 C8
  equal C5 C6
  equal C6 C7
  coincident P1 P19
  concentric C9 C10
  coincident P1 P21
  concentric C9 C12
  dimension "d1" distance P7 P8 = 31
  dimension "d2" distance P2 P3 = 37
  dimension "d3" diameter C1 = 3.4
  dimension "d4" distance L4 P11 = 3
  dimension "d5" diameter C6 = 9
  dimension "d6" diameter C9 = 30
  dimension "d7" diameter C10 = 5
  dimension "d8" diameter C11 = 8
  dimension "d9" distance C11 C12 = 2.5
extrude "Extrude1" new body sketch "Sketch1" profile of L1 L2 L3 L4 C1 C2 C3 C4 C5 C6 C7 C8 along normal blind 7 bodies "circuit_mount_stepper_simple"
extrude "Extrude4" add sketch "Sketch1" profile of L1 L2 L3 L4 C5 C6 C7 C8 C9 to an object offset -3
chamfer "Chamfer4" distance 0.5
fillet "Fillet1" radius 3
fillet "Fillet2" radius 2
chamfer "Chamfer5" distance 0.5
component_insert "Component Insert"
joint "Assemble1" alignAngle 0 alignOffsetX 0 alignOffsetY 0 alignOffsetZ 0
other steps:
joint_origin "JointOrigin1"
named bodies: "circuit_mount_stepper_simple"

design "limit_mount" references "PP_SWTC_Omron-V154"
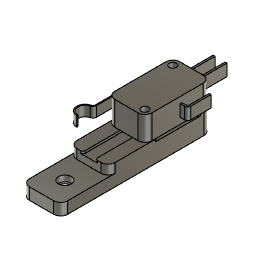
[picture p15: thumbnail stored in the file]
sketch "Sketch1" plane through (0, 0, 0) normal (0, 0, 1) x axis (1, 0, 0)
  line L1 (8.15, -10) -> (-8.15, -10)
  line L2 (8.15, 54.2) -> (8.15, -10)
  line L3 (-8.15, 54.2) -> (8.15, 54.2)
  line L4 (-8.15, -10) -> (-8.15, 54.2)
  line L5 (0, -10) -> (0, 0)
  line L6 (8.15, 10.25) -> (-8.15, 10.25)
  line L7 (-5.15, 29) -> (5.15, 29)
  line L8 (-5.15, 51.2) -> (-5.15, 29)
  line L9 (5.15, 51.2) -> (-5.15, 51.2)
  line L10 (5.15, 29) -> (5.15, 51.2)
  line L11 (0, 0) -> (0, 29)
  line L12 (-2.65, 48.7) -> (-2.65, 54.2)
  line L13 (-8.15, 48.7) -> (-2.65, 48.7)
  line L14 (2.65, 31.5) -> (8.15, 31.5)
  line L15 (2.65, 10.25) -> (2.65, 31.5)
  line L16 (-2.65, 31.5) -> (-8.15, 31.5)
  line L17 (-2.65, 10.25) -> (-2.65, 31.5)
  line L18 (2.65, 48.7) -> (2.65, 54.2)
  line L19 (8.15, 48.7) -> (2.65, 48.7)
  circle C1 centre (0, 0) radius 2.75
  circle C2 centre (-5.15, 51.2) radius 1.35
  circle C3 centre (5.15, 29) radius 1.35
  circle C4 centre (5.15, 29) radius 2.5
  circle C5 centre (-5.15, 51.2) radius 2.5
  circle C6 centre (-5.15, 29) radius 1.35
  circle C7 centre (5.15, 51.2) radius 1.35
  point P1 (0, 0)
  point P2 (0, 0)
  point P7 (0, 0)
  point P8 (0, -10)
  point P9 (-8.15, 10.25)
  point P10 (8.15, 10.25)
  point P13 (-5.15, 51.2)
  point P15 (-5.15, 51.2)
  point P11 (5.15, 29)
  point P16 (5.15, 29)
  point P17 (0, 29)
  point P18 (0, 0)
  point P19 (-2.65, 54.2)
  point P21 (-8.15, 48.7)
  point P22 (8.15, 31.5)
  point P24 (2.65, 10.25)
  point P31 (2.65, 54.2)
  point P20 (-2.65, 48.7)
  point P32 (2.65, 48.7)
  point P33 (8.15, 48.7)
  point P27 (-8.15, 31.5)
  point P23 (2.65, 31.5)
  point P28 (-2.65, 31.5)
  point P29 (-2.65, 10.25)
  point P3 (-8.15, -10)
  point P4 (8.15, -10)
  point P14 (5.15, 51.2)
  point P25 (5.15, 29)
  point P26 (-5.15, 51.2)
  coincident P1 P2
  horizontal L1
  vertical L2
  horizontal L3
  vertical L4
  coincident P1 P7
  midpoint L1 P8
  vertical L5
  coincident L4 P9
  coincident L2 P10
  perpendicular L2 L6
  horizontal L7
  vertical L8
  horizontal L9
  vertical L10
  coincident P13 P15
  coincident P11 P16
  equal C2 C3
  midpoint L7 P17
  coincident P1 P18
  vertical L11
  coincident L3 P19
  perpendicular L3 L12
  coincident L4 P21
  perpendicular L4 L13
  coincident L2 P22
  perpendicular L10 L14
  coincident L6 P24
  perpendicular L6 L15
  concentric C3 C4
  concentric C2 C5
  equal C4 C5
  tangent L12 C5
  tangent L13 C5
  tangent L14 C4
  tangent L15 C4
  symmetric C2 L11 C7
  symmetric C3 L11 C6
  symmetric L11 P19 P31
  symmetric L11 P20 P32
  symmetric L11 P21 P33
  symmetric L11 P22 P27
  symmetric L11 P23 P28
  symmetric L11 P24 P29
  dimension "d1" diameter C1 = 5.5
  dimension "d2" distance P3 P4 = 16.3
  dimension "d3" distance P7 P8 = 10
  dimension "d4" distance P1 L6 = 10.25
  dimension "d5" diameter C2 = 2.7
  dimension "d6" distance P13 P14 = 10.3
  dimension "d7" distance P11 P14 = 22.2
  dimension "d8" distance L2 L10 = 3
  dimension "d9" distance P2 P25 = 29
  dimension "d10" diameter C4 = 5
  dimension "d11" distance L3 P26 = 3
extrude "Extrude1" new body sketch "Sketch1" profile of C1 L1 L2 L3 L4 L6 C2 C3 L12 L13 L14 L15 L16 L17 C6 L18 L19 C7 against normal blind 5 bodies "limit_mount"
extrude "Extrude2" add sketch "Sketch1" profile of L2 L3 L4 L6 C2 C3 L12 L13 L14 L15 L16 L17 C6 L18 L19 C7 along normal blind 4
extrude "Extrude3" add sketch "Sketch1" profile of L2 L3 L4 L6 L12 L13 L14 L15 L16 L17 C6 L18 L19 C7 to an object offset -1
chamfer "Chamfer1" distance 2.5 distance 2.5
fillet "Fillet1" radius 3
fillet "Fillet2" radius 1
chamfer "Chamfer2" distance 0.5
component_insert "Component Insert"
joint "Assemble1" alignAngle -90 alignOffsetX 0 alignOffsetY 0 alignOffsetZ 0
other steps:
joint_origin "JointOrigin1"
named bodies: "limit_mount"

design "PP_SWTC_Omron-V154"
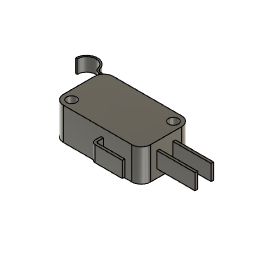
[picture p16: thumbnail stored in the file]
sketch "Sketch1" plane through (0, 0, 0) normal (0, 0, 1) x axis (1, 0, 0)
  line L1 (22.2, 0) -> (0, 0)
  line L2 (22.2, 10.3) -> (22.2, 0)
  line L3 (0, 10.3) -> (22.2, 10.3)
  line L4 (0, 0) -> (0, 10.3)
  line L5 (25, -2.8) -> (-2.8, -2.8)
  line L6 (25, 13.1) -> (25, -2.8)
  line L7 (-2.8, 13.1) -> (25, 13.1)
  line L8 (-2.8, -2.8) -> (-2.8, 13.1)
  line L9 (14.1, 15.2) -> (14.1, 13.1)
  line L10 (-6.9, 15.2) -> (14.1, 15.2)
  line L11 (13.6, 14.7) -> (-7.442, 14.7)
  line L12 (13.6, 13.1) -> (13.6, 14.7)
  line L13 (-13.9, 15.2) -> (-13.4, 15.2)
  line L14 (-10.4, 18.7) -> (-10.4, 15.2)
  line L15 (37.2, 8.1) -> (25, 8.1)
  line L16 (37.2, 7.3) -> (37.2, 8.1)
  line L17 (25, 7.3) -> (37.2, 7.3)
  line L18 (25, 8.1) -> (25, 7.3)
  line L19 (37.2, 3) -> (25, 3)
  line L20 (37.2, 2.2) -> (37.2, 3)
  line L21 (25, 2.2) -> (37.2, 2.2)
  line L22 (25, 3) -> (25, 2.2)
  line L23 (13, -5.2) -> (13, -2.8)
  line L24 (22.2, -5.2) -> (13, -5.2)
  line L25 (22.2, -6) -> (22.2, -5.2)
  line L26 (12.2, -6) -> (22.2, -6)
  line L27 (12.2, -2.8) -> (12.2, -6)
  circle C1 centre (0, 0) radius 2.8
  circle C2 centre (22.2, 10.3) radius 2.8
  circle C3 centre (22.2, 10.3) radius 1.55
  circle C4 centre (0, 0) radius 1.55
  arc A1 centre (-10.4, 15.2) radius 3.5 clockwise from (-13.9, 15.2) to (-6.9, 15.2)
  arc A2 centre (-10.4, 15.2) radius 3 clockwise from (-13.4, 15.2) to (-7.442, 14.7)
  point P1 (0, 0)
  point P2 (0, 0)
  point P10 (0, 0)
  point P4 (22.2, 10.3)
  point P11 (22.2, 10.3)
  point P13 (0, 0)
  point P14 (14.1, 13.1)
  point P18 (-13.9, 15.2)
  point P17 (-10.4, 15.2)
  point P19 (-10.4, 15.2)
  point P23 (13.6, 13.1)
  point P24 (-10.4, 15.2)
  point P25 (-10.4, 18.7)
  point P26 (25, 8.1)
  point P30 (25, 3)
  point P34 (13, -2.8)
  point P39 (12.2, -2.8)
  point P31 (37.2, 3)
  point P3 (22.2, 0)
  point P6 (-2.8, -2.8)
  point P7 (25, -2.8)
  point P9 (-2.8, 13.1)
  point P8 (25, 13.1)
  point P12 (22.2, 10.3)
  point P22 (13.6, 14.7)
  point P15 (14.1, 15.2)
  point P35 (13, -5.2)
  point P32 (37.2, 2.2)
  point P27 (37.2, 8.1)
  point P28 (37.2, 7.3)
  point P37 (22.2, -6)
  horizontal L1
  vertical L2
  horizontal L3
  vertical L4
  coincident P1 P2
  horizontal L5
  vertical L6
  horizontal L7
  vertical L8
  coincident P1 P10
  coincident P4 P11
  concentric C2 C3
  coincident P1 P13
  equal C3 C4
  tangent L7 C2
  tangent L6 C2
  tangent L5 C1
  coincident L7 P14
  perpendicular L7 L9
  perpendicular L9 L10
  coincident L10 P18
  coincident P17 P19
  horizontal L11
  coincident L7 P23
  perpendicular L7 L12
  coincident P19 L13
  horizontal L13
  coincident P19 P24
  midpoint A1 P25
  horizontal L15
  vertical L16
  horizontal L17
  vertical L18
  coincident L6 P26
  horizontal L19
  vertical L20
  horizontal L21
  vertical L22
  coincident L6 P30
  coincident L5 P34
  perpendicular L5 L23
  perpendicular L6 L24
  perpendicular L24 L25
  perpendicular L25 L26
  coincident L5 P39
  perpendicular L5 L27
  coincident L16 P31
  dimension "d2" distance P2 P3 = 22.2
  dimension "d3" distance P3 P4 = 10.3
  dimension "d4" distance P6 P7 = 27.8
  dimension "d5" distance P6 P9 = 15.9
  dimension "d6" diameter C3 = 3.1
  dimension "d7" distance P8 P12 = 2.8
  dimension "d8" distance L9 L12 = 0.5
  dimension "d9" distance L10 P22 = 0.5 (= "d8")
  dimension "d10" distance A1 A2 = 0.5 (= "d8")
  dimension "d11" radius A1 = 3.5
  dimension "d12" distance P10 P25 = 18.7
  dimension "d13" distance P12 P25 = 32.6
  dimension "d14" distance P12 P15 = 8.1
  dimension "d25" distance P35 L27 = 0.8
  dimension "d26" distance P35 L26 = 0.8 (= "d25")
  dimension "d27" distance P31 P32 = 0.8 (= "d25")
  dimension "d28" distance P27 P28 = 0.8 (= "d25")
  dimension "d29" distance P8 P37 = 19.1
  dimension "d30" distance P7 P37 = 2.8
  dimension "d31" distance P7 L23 = 12
  dimension "d33" distance P8 P27 = 5
  dimension "d34" distance P6 P28 = 40
  dimension "d35" distance P7 P32 = 5 (= "d33")
extrude "Extrude1" new body sketch "Sketch1" profile of L5 L6 L7 L8 C3 C4 distance 10.3
extrude "Extrude2" add sketch "Sketch1" profile of L7 L9 L10 A1 A2 L11 L12 L13 distance 4.3
fillet "Fillet1" radius 3
fillet "Fillet2" radius 1
fillet "Fillet3" radius 1.5
extrude "Extrude3" add sketch "Sketch1" profile of L5 L6 L15 L16 L17 L18 L19 L20 L21 L22 L23 L24 L25 L26 L27 distance 5
fillet "Fillet4" radius 0.5
fillet "Fillet5" radius 1.3 (= "0.5 mm + 0.8 mm")

design "HW_M3-Washer"
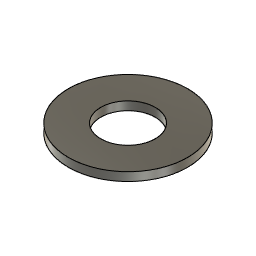
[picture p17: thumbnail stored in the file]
sketch "Sketch1" plane through (0, 0, 0) normal (0, 1, 0) x axis (1, 0, 0)
  line L1 (3.5, 0) -> (1.6, 0)
  line L2 (3.5, -0.5) -> (3.5, 0)
  line L3 (1.6, -0.5) -> (3.5, -0.5)
  line L4 (1.6, 0) -> (1.6, -0.5)
  point P1 (0, 0)
  point P2 (1.6, 0)
  point P5 (1.6, -0.5)
  horizontal L1
  vertical L2
  horizontal L3
  vertical L4
  coincident P1 L1
  dimension "d1" distance P2 P5 = 0.5
  dimension "d2" distance P1 L4 = 1.6 (= "( 3.2 / 2 ) * 1 mm")
  dimension "d3" distance P1 L2 = 3.5 (= "( 7 / 2 ) * 1 mm")
revolve "Revolve1" sketch "Sketch1" AlongAngle 360

design "leadscrew_motor_mount"
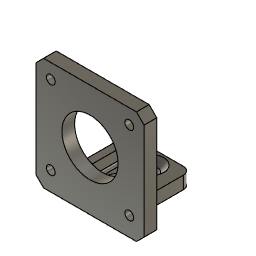
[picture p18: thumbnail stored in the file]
sketch "Sketch2" plane through (0, 0, 0) normal (0, 1, 0) x axis (1, 0, 0)
  line L1 (10, 0) -> (-10, 0)
  line L2 (10, 20) -> (10, 0)
  line L3 (-10, 20) -> (10, 20)
  line L4 (-10, 0) -> (-10, 20)
  line L5 (10, 20) -> (-10, 0)
  line L6 (-21.15, -44.15) -> (21.15, -44.15)
  line L7 (-21.15, -1.85) -> (-21.15, -44.15)
  line L8 (21.15, -1.85) -> (-21.15, -1.85)
  line L9 (21.15, -44.15) -> (21.15, -1.85)
  line L10 (-21.15, -1.85) -> (21.15, -44.15)
  line L11 (21.15, -1.85) -> (-21.15, -44.15)
  line L12 (0, 0) -> (0, -23)
  line L13 (15.5, -38.5) -> (-15.5, -38.5)
  line L14 (15.5, -7.5) -> (15.5, -38.5)
  line L15 (-15.5, -7.5) -> (15.5, -7.5)
  line L16 (-15.5, -38.5) -> (-15.5, -7.5)
  line L17 (21.35, -44.35) -> (-21.35, -44.35)
  line L18 (21.35, 0) -> (21.35, -44.35)
  line L19 (-21.35, 0) -> (21.35, 0)
  line L20 (-21.35, -44.35) -> (-21.35, 0)
  line L21 (9.9, -5) -> (9.9, 0)
  line L22 (-9.9, -5) -> (9.9, -5)
  line L23 (-9.9, 0) -> (-9.9, -5)
  line L24 (-6.9, -10) -> (-6.9, -5)
  line L25 (-9.9, -10) -> (-6.9, -10)
  line L26 (-9.9, -5) -> (-9.9, -10)
  circle C1 centre (0, -23) radius 11.1
  circle C2 centre (-15.5, -38.5) radius 1.75
  circle C3 centre (15.5, -38.5) radius 1.75
  circle C4 centre (-15.5, -7.5) radius 1.75
  circle C5 centre (15.5, -7.5) radius 1.75
  circle C6 centre (-15.5, -7.5) radius 3.5
  circle C7 centre (15.5, -7.5) radius 3.5
  point P1 (0, 0)
  point P10 (0, -23)
  point P11 (0, -23)
  point P12 (0, -23)
  point P13 (0, 0)
  point P16 (15.5, -7.5)
  point P14 (-15.5, -38.5)
  point P15 (15.5, -38.5)
  point P18 (-15.5, -38.5)
  point P19 (15.5, -38.5)
  point P17 (-15.5, -7.5)
  point P20 (-15.5, -7.5)
  point P21 (15.5, -7.5)
  point P26 (9.9, 0)
  point P29 (-9.9, 0)
  point P30 (0, -5)
  point P31 (-15.5, -7.5)
  point P32 (15.5, -7.5)
  point P27 (9.9, -5)
  point P33 (9.9, -5)
  point P34 (-6.9, -5)
  point P28 (-9.9, -5)
  point P37 (-9.9, -5)
  point P4 (10, 20)
  point P5 (-10, 20)
  point P6 (21.15, -44.15)
  point P7 (-21.15, -44.15)
  point P9 (21.15, -1.85)
  point P35 (-6.9, -10)
  point P36 (-9.9, -10)
  point P2 (-10, 0)
  horizontal L1
  vertical L2
  horizontal L3
  vertical L4
  midpoint P1 L1
  equal L1 L4
  horizontal L6
  perpendicular L6 L7
  parallel L6 L8
  parallel L7 L9
  coincident L10 P10
  coincident L11 P10
  equal L6 L9
  coincident P10 P11
  coincident P11 P12
  coincident P1 P13
  vertical L12
  horizontal L13
  vertical L14
  horizontal L15
  vertical L16
  coincident L11 P16
  coincident L11 P14
  coincident L10 P15
  equal C2 C3
  equal C2 C5
  equal C4 C5
  coincident P14 P18
  coincident P15 P19
  coincident P17 P20
  coincident P16 P21
  horizontal L17
  vertical L18
  horizontal L19
  vertical L20
  midpoint P1 L19
  coincident L19 P26
  perpendicular L15 L21
  perpendicular L21 L22
  coincident L19 P29
  perpendicular L19 L23
  midpoint L22 P30
  coincident L12 P30
  equal C6 C7
  coincident P20 P31
  coincident P21 P32
  coincident P27 P33
  coincident L22 P34
  perpendicular L22 L24
  perpendicular L24 L25
  perpendicular L25 L26
  coincident P28 P37
  dimension "d1" distance P4 P5 = 20
  dimension "d2" distance P6 P7 = 42.3
  dimension "d3" diameter C1 = 22.2
  dimension "d4" distance P12 P13 = 23
  dimension "d5" distance P14 P15 = 31
  dimension "d6" diameter C2 = 3.5
  dimension "d7" distance P9 L18 = 0.2
  dimension "d8" distance P27 P28 = 19.8
  dimension "d9" distance P26 P27 = 5
  dimension "d10" distance P6 L17 = 0.2 (= "d7")
  dimension "d29" diameter C6 = 7
  dimension "d39" distance P35 P36 = 3
  dimension "d40" distance P2 P36 = 10
extrude "Extrude1" new body sketch "Sketch2" profile of C1 C2 C3 C4 C5 L17 L18 L19 L20 L21 L22 L23 against normal blind 5 bodies "leadscrew_motor_mount"
extrude "Extrude2" add sketch "Sketch2" profile of L19 L21 L22 L23 along normal blind 25
sketch "Sketch3" plane through (0, 0, 5) normal (0, 0, 1) x axis (-1, 0, 0)
  line L1 (-9.9, 0) -> (9.9, 0)
  line L2 (9.9, -25) -> (-9.9, -25)
  line L3 (9.9, 0) -> (9.9, -25)
  line L4 (0, 0) -> (0, -25)
  line L5 (-9.9, -25) -> (-9.9, 0)
  circle C1 centre (0, -6) radius 2.75
  circle C2 centre (0, -19) radius 2.75
  circle C3 centre (0, -6) radius 5.125
  circle C4 centre (0, -19) radius 5.125
  point P1 (0, 0)
  point P7 (0, 0)
  point P8 (0, -6)
  point P9 (0, -19)
  point P6 (0, -25)
  point P11 (0, -19)
  point P10 (0, -6)
  coincident P1 P7
  coincident L4 P8
  coincident L4 P9
  concentric C1 C3
  concentric C2 C4
  equal C3 C4
  equal C1 C2
  coincident L2 P6
  perpendicular L2 L4
  dimension "d15" distance P1 P8 = 6
  dimension "d16" diameter C3 = 10.25
  dimension "d18" diameter C1 = 5.5
  dimension "d22" distance P6 P11 = 6 (= "d15")
  dimension "d23" distance P10 P11 = 13
extrude "Extrude3" cut sketch "Sketch3" profile of C1 C2 to an object
extrude "Extrude6" add sketch "Sketch2" profile of L22 L24 L25 L26 to an object
fillet "Fillet5" radius 3
fillet "Fillet6" radius 1
extrude "Extrude4" cut sketch "Sketch2" profile of C4 C5 C6 C7 no distance stored
extrude "Extrude5" cut sketch "Sketch3" profile of C1 C3 no distance stored
chamfer "Chamfer3" distance 2.375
